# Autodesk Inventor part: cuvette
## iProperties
Shininess: 20.0
Angle Display Precision: 2
Document Length Units: 11269
Document Angle Units: 11279
Document Time Units: 11290
Document Mass Units: 11283
Document Length Units Precision: 3
Document Angle Units Precision: 2
Compacted: True
Created: 2002-04
Part Number: cuvette
Material: Par défaut
Document SubType Name: Modélisation
Designer: thchene
Density: 0.0
Volumn: 0.0
Area: 0.0
PropertySet Name: Model Information
Control State: 0
Master: False
Checked Out: False
Author: thchene
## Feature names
1. Révolution1 [Revolution]
